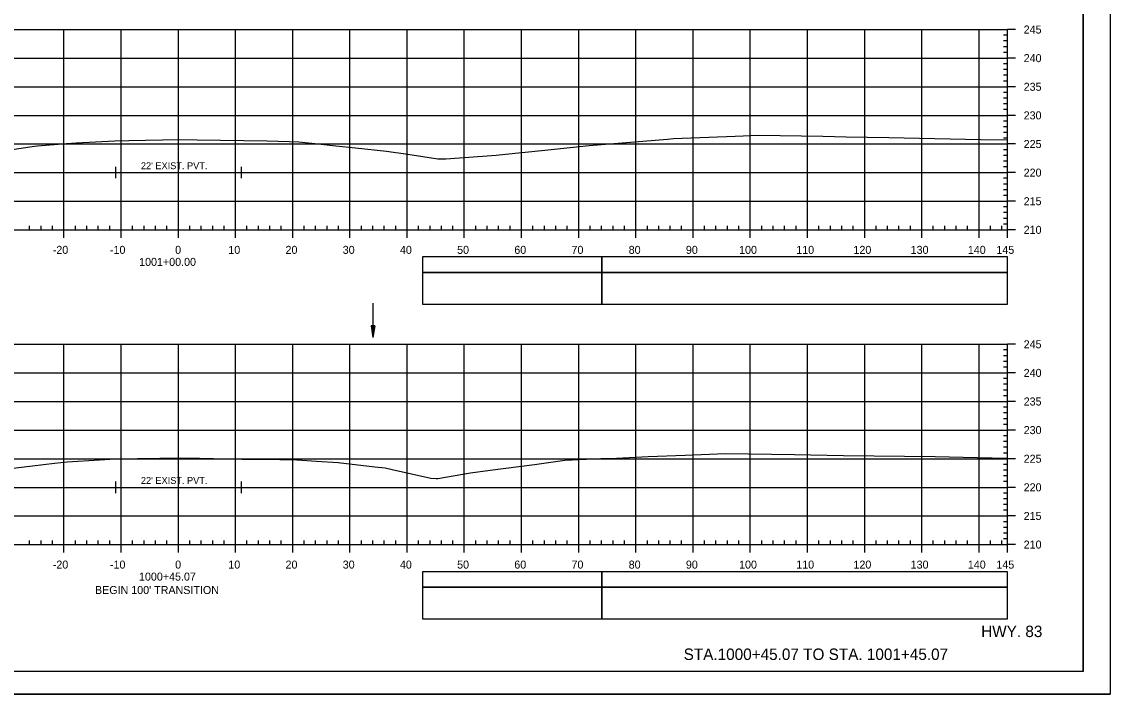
# Model space of a CAD drawing. Extents: x 1386544 to 1388153, y 379785 to 390999.
# Drawn here: x 1387350.6 to 1387540.9, y 379784.8 to 379902.3 of the extents above; entities that cross this region are included whole.
import ezdxf

# ---------------------------------------------------------------- set-up
doc = ezdxf.new("R2010")
doc.units = 0
for name, color, linetype in [('R_Alt Surface', 7, 'Continuous'), ('R_Axis', 7, 'Continuous'), ('R_Axis Annot', 7, 'Continuous'), ('R_Border', 7, 'Continuous'), ('R_Draft', 7, 'Continuous'), ('R_Exist Surface', 7, 'Continuous'), ('R_Grid', 7, 'Continuous'), ('R_No Plot', 7, 'Continuous'), ('R_Striping', 7, 'Continuous'), ('R_Water', 7, 'Continuous')]:
    doc.layers.add(name, color=color, linetype=linetype)

msp = doc.modelspace()

# ---------------------------------------------------------------- linework, layer by layer
at = {"layer": 'R_Alt Surface'}
for points in [[(1387366.95, 379876.95), (1387366.95, 379874.95)], [(1387388.95, 379876.95), (1387388.95, 379874.95)], [(1387366.95, 379875.95), (1387388.95, 379875.95)], [(1387366.95, 379821.95), (1387366.95, 379819.95)], [(1387388.95, 379821.95), (1387388.95, 379819.95)], [(1387366.95, 379820.95), (1387388.95, 379820.95)]]:
    msp.add_lwpolyline(points, dxfattribs=at)
at = {"layer": 'R_Axis'}
for p, q in [((1387522.95, 379899.95), (1387522.25, 379899.95)), ((1387522.95, 379865.95), (1387522.95, 379900.95)), ((1387524.35, 379900.95), (1387522.95, 379900.95)), ((1387522.95, 379898.95), (1387522.25, 379898.95)), ((1387522.95, 379897.95), (1387522.25, 379897.95)), ((1387522.95, 379896.95), (1387522.25, 379896.95)), ((1387522.95, 379894.95), (1387522.25, 379894.95)), ((1387524.35, 379895.95), (1387522.95, 379895.95)), ((1387522.95, 379893.95), (1387522.25, 379893.95)), ((1387522.95, 379892.95), (1387522.25, 379892.95)), ((1387522.95, 379891.95), (1387522.25, 379891.95)), ((1387524.35, 379890.95), (1387522.95, 379890.95)), ((1387522.95, 379889.95), (1387522.25, 379889.95)), ((1387522.95, 379888.95), (1387522.25, 379888.95)), ((1387522.95, 379887.95), (1387522.25, 379887.95)), ((1387522.95, 379886.95), (1387522.25, 379886.95)), ((1387522.95, 379884.95), (1387522.25, 379884.95)), ((1387524.35, 379885.95), (1387522.95, 379885.95)), ((1387522.95, 379883.95), (1387522.25, 379883.95)), ((1387522.95, 379882.95), (1387522.25, 379882.95)), ((1387522.95, 379881.95), (1387522.25, 379881.95)), ((1387524.35, 379880.95), (1387522.95, 379880.95)), ((1387522.95, 379879.95), (1387522.25, 379879.95)), ((1387522.95, 379878.95), (1387522.25, 379878.95)), ((1387522.95, 379877.95), (1387522.25, 379877.95)), ((1387522.95, 379876.95), (1387522.25, 379876.95)), ((1387524.35, 379875.95), (1387522.95, 379875.95)), ((1387522.95, 379874.95), (1387522.25, 379874.95)), ((1387522.95, 379873.95), (1387522.25, 379873.95)), ((1387522.95, 379872.95), (1387522.25, 379872.95)), ((1387522.95, 379871.95), (1387522.25, 379871.95)), ((1387522.95, 379869.95), (1387522.25, 379869.95)), ((1387524.35, 379870.95), (1387522.95, 379870.95)), ((1387522.95, 379868.95), (1387522.25, 379868.95)), ((1387522.95, 379867.95), (1387522.25, 379867.95)), ((1387232.95, 379865.95), (1387522.95, 379865.95)), ((1387351.95, 379865.95), (1387351.95, 379866.65)), ((1387353.95, 379865.95), (1387353.95, 379866.65)), ((1387355.95, 379865.95), (1387355.95, 379866.65)), ((1387357.95, 379864.55), (1387357.95, 379865.95)), ((1387359.95, 379865.95), (1387359.95, 379866.65)), ((1387361.95, 379865.95), (1387361.95, 379866.65)), ((1387363.95, 379865.95), (1387363.95, 379866.65)), ((1387365.95, 379865.95), (1387365.95, 379866.65)), ((1387367.95, 379864.55), (1387367.95, 379865.95)), ((1387369.95, 379865.95), (1387369.95, 379866.65)), ((1387371.95, 379865.95), (1387371.95, 379866.65)), ((1387373.95, 379865.95), (1387373.95, 379866.65)), ((1387375.95, 379865.95), (1387375.95, 379866.65)), ((1387377.95, 379864.55), (1387377.95, 379865.95)), ((1387379.95, 379865.95), (1387379.95, 379866.65)), ((1387381.95, 379865.95), (1387381.95, 379866.65)), ((1387383.95, 379865.95), (1387383.95, 379866.65)), ((1387385.95, 379865.95), (1387385.95, 379866.65)), ((1387387.95, 379864.55), (1387387.95, 379865.95)), ((1387389.95, 379865.95), (1387389.95, 379866.65)), ((1387391.95, 379865.95), (1387391.95, 379866.65)), ((1387393.95, 379865.95), (1387393.95, 379866.65)), ((1387395.95, 379865.95), (1387395.95, 379866.65)), ((1387397.95, 379864.55), (1387397.95, 379865.95)), ((1387399.95, 379865.95), (1387399.95, 379866.65)), ((1387401.95, 379865.95), (1387401.95, 379866.65)), ((1387403.95, 379865.95), (1387403.95, 379866.65)), ((1387405.95, 379865.95), (1387405.95, 379866.65)), ((1387407.95, 379864.55), (1387407.95, 379865.95)), ((1387409.95, 379865.95), (1387409.95, 379866.65)), ((1387411.95, 379865.95), (1387411.95, 379866.65)), ((1387413.95, 379865.95), (1387413.95, 379866.65)), ((1387415.95, 379865.95), (1387415.95, 379866.65)), ((1387417.95, 379864.55), (1387417.95, 379865.95)), ((1387419.95, 379865.95), (1387419.95, 379866.65)), ((1387421.95, 379865.95), (1387421.95, 379866.65)), ((1387423.95, 379865.95), (1387423.95, 379866.65)), ((1387425.95, 379865.95), (1387425.95, 379866.65)), ((1387427.95, 379864.55), (1387427.95, 379865.95)), ((1387429.95, 379865.95), (1387429.95, 379866.65)), ((1387431.95, 379865.95), (1387431.95, 379866.65)), ((1387433.95, 379865.95), (1387433.95, 379866.65)), ((1387435.95, 379865.95), (1387435.95, 379866.65)), ((1387437.95, 379864.55), (1387437.95, 379865.95)), ((1387439.95, 379865.95), (1387439.95, 379866.65)), ((1387441.95, 379865.95), (1387441.95, 379866.65)), ((1387443.95, 379865.95), (1387443.95, 379866.65)), ((1387445.95, 379865.95), (1387445.95, 379866.65)), ((1387447.95, 379864.55), (1387447.95, 379865.95)), ((1387449.95, 379865.95), (1387449.95, 379866.65)), ((1387451.95, 379865.95), (1387451.95, 379866.65)), ((1387453.95, 379865.95), (1387453.95, 379866.65)), ((1387455.95, 379865.95), (1387455.95, 379866.65)), ((1387457.95, 379864.55), (1387457.95, 379865.95)), ((1387459.95, 379865.95), (1387459.95, 379866.65)), ((1387461.95, 379865.95), (1387461.95, 379866.65)), ((1387463.95, 379865.95), (1387463.95, 379866.65)), ((1387465.95, 379865.95), (1387465.95, 379866.65)), ((1387467.95, 379864.55), (1387467.95, 379865.95)), ((1387469.95, 379865.95), (1387469.95, 379866.65)), ((1387471.95, 379865.95), (1387471.95, 379866.65)), ((1387473.95, 379865.95), (1387473.95, 379866.65)), ((1387475.95, 379865.95), (1387475.95, 379866.65)), ((1387477.95, 379864.55), (1387477.95, 379865.95)), ((1387479.95, 379865.95), (1387479.95, 379866.65)), ((1387481.95, 379865.95), (1387481.95, 379866.65)), ((1387483.95, 379865.95), (1387483.95, 379866.65)), ((1387485.95, 379865.95), (1387485.95, 379866.65)), ((1387487.95, 379864.55), (1387487.95, 379865.95)), ((1387489.95, 379865.95), (1387489.95, 379866.65)), ((1387491.95, 379865.95), (1387491.95, 379866.65)), ((1387493.95, 379865.95), (1387493.95, 379866.65)), ((1387495.95, 379865.95), (1387495.95, 379866.65)), ((1387497.95, 379864.55), (1387497.95, 379865.95)), ((1387499.95, 379865.95), (1387499.95, 379866.65)), ((1387501.95, 379865.95), (1387501.95, 379866.65)), ((1387503.95, 379865.95), (1387503.95, 379866.65)), ((1387505.95, 379865.95), (1387505.95, 379866.65)), ((1387507.95, 379864.55), (1387507.95, 379865.95)), ((1387509.95, 379865.95), (1387509.95, 379866.65)), ((1387511.95, 379865.95), (1387511.95, 379866.65)), ((1387513.95, 379865.95), (1387513.95, 379866.65)), ((1387515.95, 379865.95), (1387515.95, 379866.65)), ((1387517.95, 379864.55), (1387517.95, 379865.95)), ((1387519.95, 379865.95), (1387519.95, 379866.65)), ((1387521.95, 379865.95), (1387521.95, 379866.65)), ((1387522.95, 379866.95), (1387522.25, 379866.95)), ((1387522.95, 379864.55), (1387522.95, 379865.95)), ((1387524.35, 379865.95), (1387522.95, 379865.95)), ((1387522.95, 379844.95), (1387522.25, 379844.95)), ((1387522.95, 379810.95), (1387522.95, 379845.95)), ((1387524.35, 379845.95), (1387522.95, 379845.95)), ((1387522.95, 379843.95), (1387522.25, 379843.95)), ((1387522.95, 379842.95), (1387522.25, 379842.95)), ((1387522.95, 379841.95), (1387522.25, 379841.95)), ((1387524.35, 379840.95), (1387522.95, 379840.95)), ((1387522.95, 379839.95), (1387522.25, 379839.95)), ((1387522.95, 379838.95), (1387522.25, 379838.95)), ((1387522.95, 379837.95), (1387522.25, 379837.95)), ((1387522.95, 379836.95), (1387522.25, 379836.95)), ((1387524.35, 379835.95), (1387522.95, 379835.95)), ((1387522.95, 379834.95), (1387522.25, 379834.95)), ((1387522.95, 379833.95), (1387522.25, 379833.95)), ((1387522.95, 379832.95), (1387522.25, 379832.95)), ((1387522.95, 379831.95), (1387522.25, 379831.95)), ((1387522.95, 379829.95), (1387522.25, 379829.95)), ((1387524.35, 379830.95), (1387522.95, 379830.95)), ((1387522.95, 379828.95), (1387522.25, 379828.95)), ((1387522.95, 379827.95), (1387522.25, 379827.95)), ((1387522.95, 379826.95), (1387522.25, 379826.95)), ((1387524.35, 379825.95), (1387522.95, 379825.95)), ((1387522.95, 379824.95), (1387522.25, 379824.95)), ((1387522.95, 379823.95), (1387522.25, 379823.95)), ((1387522.95, 379822.95), (1387522.25, 379822.95)), ((1387522.95, 379821.95), (1387522.25, 379821.95)), ((1387522.95, 379819.95), (1387522.25, 379819.95)), ((1387524.35, 379820.95), (1387522.95, 379820.95)), ((1387522.95, 379818.95), (1387522.25, 379818.95)), ((1387522.95, 379817.95), (1387522.25, 379817.95)), ((1387522.95, 379816.95), (1387522.25, 379816.95)), ((1387522.95, 379814.95), (1387522.25, 379814.95)), ((1387524.35, 379815.95), (1387522.95, 379815.95)), ((1387522.95, 379813.95), (1387522.25, 379813.95)), ((1387522.95, 379812.95), (1387522.25, 379812.95)), ((1387232.95, 379810.95), (1387522.95, 379810.95)), ((1387351.95, 379810.95), (1387351.95, 379811.65)), ((1387353.95, 379810.95), (1387353.95, 379811.65)), ((1387355.95, 379810.95), (1387355.95, 379811.65)), ((1387357.95, 379809.55), (1387357.95, 379810.95)), ((1387359.95, 379810.95), (1387359.95, 379811.65)), ((1387361.95, 379810.95), (1387361.95, 379811.65)), ((1387363.95, 379810.95), (1387363.95, 379811.65)), ((1387365.95, 379810.95), (1387365.95, 379811.65)), ((1387367.95, 379809.55), (1387367.95, 379810.95)), ((1387369.95, 379810.95), (1387369.95, 379811.65)), ((1387371.95, 379810.95), (1387371.95, 379811.65)), ((1387373.95, 379810.95), (1387373.95, 379811.65)), ((1387375.95, 379810.95), (1387375.95, 379811.65)), ((1387377.95, 379809.55), (1387377.95, 379810.95)), ((1387379.95, 379810.95), (1387379.95, 379811.65)), ((1387381.95, 379810.95), (1387381.95, 379811.65)), ((1387383.95, 379810.95), (1387383.95, 379811.65)), ((1387385.95, 379810.95), (1387385.95, 379811.65)), ((1387387.95, 379809.55), (1387387.95, 379810.95)), ((1387389.95, 379810.95), (1387389.95, 379811.65)), ((1387391.95, 379810.95), (1387391.95, 379811.65)), ((1387393.95, 379810.95), (1387393.95, 379811.65)), ((1387395.95, 379810.95), (1387395.95, 379811.65)), ((1387397.95, 379809.55), (1387397.95, 379810.95)), ((1387399.95, 379810.95), (1387399.95, 379811.65)), ((1387401.95, 379810.95), (1387401.95, 379811.65)), ((1387403.95, 379810.95), (1387403.95, 379811.65)), ((1387405.95, 379810.95), (1387405.95, 379811.65)), ((1387407.95, 379809.55), (1387407.95, 379810.95)), ((1387409.95, 379810.95), (1387409.95, 379811.65)), ((1387411.95, 379810.95), (1387411.95, 379811.65)), ((1387413.95, 379810.95), (1387413.95, 379811.65)), ((1387415.95, 379810.95), (1387415.95, 379811.65)), ((1387417.95, 379809.55), (1387417.95, 379810.95)), ((1387419.95, 379810.95), (1387419.95, 379811.65)), ((1387421.95, 379810.95), (1387421.95, 379811.65)), ((1387423.95, 379810.95), (1387423.95, 379811.65)), ((1387425.95, 379810.95), (1387425.95, 379811.65)), ((1387427.95, 379809.55), (1387427.95, 379810.95)), ((1387429.95, 379810.95), (1387429.95, 379811.65)), ((1387431.95, 379810.95), (1387431.95, 379811.65)), ((1387433.95, 379810.95), (1387433.95, 379811.65)), ((1387435.95, 379810.95), (1387435.95, 379811.65)), ((1387437.95, 379809.55), (1387437.95, 379810.95)), ((1387439.95, 379810.95), (1387439.95, 379811.65)), ((1387441.95, 379810.95), (1387441.95, 379811.65)), ((1387443.95, 379810.95), (1387443.95, 379811.65)), ((1387445.95, 379810.95), (1387445.95, 379811.65)), ((1387447.95, 379809.55), (1387447.95, 379810.95)), ((1387449.95, 379810.95), (1387449.95, 379811.65)), ((1387451.95, 379810.95), (1387451.95, 379811.65)), ((1387453.95, 379810.95), (1387453.95, 379811.65)), ((1387455.95, 379810.95), (1387455.95, 379811.65)), ((1387457.95, 379809.55), (1387457.95, 379810.95)), ((1387459.95, 379810.95), (1387459.95, 379811.65)), ((1387461.95, 379810.95), (1387461.95, 379811.65)), ((1387463.95, 379810.95), (1387463.95, 379811.65)), ((1387465.95, 379810.95), (1387465.95, 379811.65)), ((1387467.95, 379809.55), (1387467.95, 379810.95)), ((1387469.95, 379810.95), (1387469.95, 379811.65)), ((1387471.95, 379810.95), (1387471.95, 379811.65)), ((1387473.95, 379810.95), (1387473.95, 379811.65)), ((1387475.95, 379810.95), (1387475.95, 379811.65)), ((1387477.95, 379809.55), (1387477.95, 379810.95)), ((1387479.95, 379810.95), (1387479.95, 379811.65)), ((1387481.95, 379810.95), (1387481.95, 379811.65)), ((1387483.95, 379810.95), (1387483.95, 379811.65)), ((1387485.95, 379810.95), (1387485.95, 379811.65)), ((1387487.95, 379809.55), (1387487.95, 379810.95)), ((1387489.95, 379810.95), (1387489.95, 379811.65)), ((1387491.95, 379810.95), (1387491.95, 379811.65)), ((1387493.95, 379810.95), (1387493.95, 379811.65)), ((1387495.95, 379810.95), (1387495.95, 379811.65)), ((1387497.95, 379809.55), (1387497.95, 379810.95)), ((1387499.95, 379810.95), (1387499.95, 379811.65)), ((1387501.95, 379810.95), (1387501.95, 379811.65)), ((1387503.95, 379810.95), (1387503.95, 379811.65)), ((1387505.95, 379810.95), (1387505.95, 379811.65)), ((1387507.95, 379809.55), (1387507.95, 379810.95)), ((1387509.95, 379810.95), (1387509.95, 379811.65)), ((1387511.95, 379810.95), (1387511.95, 379811.65)), ((1387513.95, 379810.95), (1387513.95, 379811.65)), ((1387515.95, 379810.95), (1387515.95, 379811.65)), ((1387517.95, 379809.55), (1387517.95, 379810.95)), ((1387519.95, 379810.95), (1387519.95, 379811.65)), ((1387521.95, 379810.95), (1387521.95, 379811.65)), ((1387522.95, 379811.95), (1387522.25, 379811.95)), ((1387522.95, 379809.55), (1387522.95, 379810.95)), ((1387524.35, 379810.95), (1387522.95, 379810.95))]:
    msp.add_line(p, q, dxfattribs=at)
at = {"layer": 'R_Axis Annot'}
for points in [[(1387451.97, 379858.5), (1387522.95, 379858.5), (1387522.95, 379861.21), (1387451.97, 379861.21)], [(1387451.97, 379852.98), (1387522.95, 379852.98), (1387522.95, 379858.5), (1387451.97, 379858.5)], [(1387451.97, 379803.5), (1387522.95, 379803.5), (1387522.95, 379806.21), (1387451.97, 379806.21)], [(1387451.97, 379797.98), (1387522.95, 379797.98), (1387522.95, 379803.5), (1387451.97, 379803.5)]]:
    msp.add_lwpolyline(points, close=True, dxfattribs=at)
at = {"layer": 'R_Border'}
for q in [(1387536.13, 379994.24), (1387219.95, 379788.78)]:
    msp.add_line((1387536.13, 379788.78), q, dxfattribs=at)
at = {"layer": 'R_Exist Surface'}
for points in [[(1387337.3, 379878.22), (1387351.98, 379880.44), (1387352.77, 379880.56), (1387353.33, 379880.61), (1387358.41, 379881.06), (1387360.08, 379881.16), (1387366.83, 379881.51), (1387369.28, 379881.55), (1387378.08, 379881.71), (1387381.21, 379881.67), (1387393.48, 379881.49), (1387397.31, 379881.4), (1387399.01, 379881.35), (1387402.42, 379880.97), (1387405.46, 379880.64), (1387408.92, 379880.28), (1387414.33, 379879.71), (1387418.08, 379879.15), (1387423.33, 379878.38), (1387424.19, 379878.38), (1387424.73, 379878.38), (1387433.51, 379879), (1387435.12, 379879.15), (1387441.47, 379879.8), (1387449.76, 379880.66), (1387463.5, 379881.79), (1387464.54, 379881.89), (1387475.28, 379882.33), (1387479.47, 379882.52), (1387490.66, 379882.3), (1387494.74, 379882.21), (1387502.18, 379882.06), (1387518.27, 379881.74), (1387522.95, 379881.68)], [(1387338.29, 379822.99), (1387352.44, 379824.68), (1387356.28, 379825.16), (1387358.49, 379825.42), (1387364.18, 379825.76), (1387366.91, 379825.94), (1387374.69, 379826.07), (1387378.24, 379826.12), (1387381.63, 379826.05), (1387389.07, 379825.89), (1387395.72, 379825.81), (1387398.65, 379825.76), (1387402.09, 379825.5), (1387405.92, 379825.27), (1387412.31, 379824.52), (1387414.08, 379824.33), (1387415.32, 379824.07), (1387422.09, 379822.54), (1387423.02, 379822.48), (1387423.33, 379822.47), (1387429.04, 379823.46), (1387432.44, 379823.93), (1387440.24, 379824.95), (1387445.52, 379825.72), (1387451.79, 379825.99), (1387454.53, 379826.07), (1387460.09, 379826.33), (1387466.59, 379826.6), (1387473.62, 379826.88), (1387485.7, 379826.7), (1387494.26, 379826.53), (1387510.28, 379826.31), (1387517.6, 379826.17), (1387522.95, 379826.05)]]:
    msp.add_lwpolyline(points, dxfattribs=at)
at = {"layer": 'R_Grid'}
for p, q in [((1387232.95, 379900.95), (1387522.95, 379900.95)), ((1387357.95, 379865.95), (1387357.95, 379900.95)), ((1387367.95, 379865.95), (1387367.95, 379900.95)), ((1387377.95, 379865.95), (1387377.95, 379900.95)), ((1387387.95, 379865.95), (1387387.95, 379900.95)), ((1387397.95, 379865.95), (1387397.95, 379900.95)), ((1387407.95, 379865.95), (1387407.95, 379900.95)), ((1387417.95, 379865.95), (1387417.95, 379900.95)), ((1387427.95, 379865.95), (1387427.95, 379900.95)), ((1387437.95, 379865.95), (1387437.95, 379900.95)), ((1387447.95, 379865.95), (1387447.95, 379900.95)), ((1387457.95, 379865.95), (1387457.95, 379900.95)), ((1387467.95, 379865.95), (1387467.95, 379900.95)), ((1387477.95, 379865.95), (1387477.95, 379900.95)), ((1387487.95, 379865.95), (1387487.95, 379900.95)), ((1387497.95, 379865.95), (1387497.95, 379900.95)), ((1387507.95, 379865.95), (1387507.95, 379900.95)), ((1387517.95, 379865.95), (1387517.95, 379900.95)), ((1387522.95, 379865.95), (1387522.95, 379900.95)), ((1387232.95, 379895.95), (1387522.95, 379895.95)), ((1387232.95, 379890.95), (1387522.95, 379890.95)), ((1387232.95, 379885.95), (1387522.95, 379885.95)), ((1387232.95, 379880.95), (1387522.95, 379880.95)), ((1387232.95, 379875.95), (1387522.95, 379875.95)), ((1387232.95, 379870.95), (1387522.95, 379870.95)), ((1387232.95, 379865.95), (1387522.95, 379865.95)), ((1387232.95, 379845.95), (1387522.95, 379845.95)), ((1387357.95, 379810.95), (1387357.95, 379845.95)), ((1387367.95, 379810.95), (1387367.95, 379845.95)), ((1387377.95, 379810.95), (1387377.95, 379845.95)), ((1387387.95, 379810.95), (1387387.95, 379845.95)), ((1387397.95, 379810.95), (1387397.95, 379845.95)), ((1387407.95, 379810.95), (1387407.95, 379845.95)), ((1387417.95, 379810.95), (1387417.95, 379845.95)), ((1387427.95, 379810.95), (1387427.95, 379845.95)), ((1387437.95, 379810.95), (1387437.95, 379845.95)), ((1387447.95, 379810.95), (1387447.95, 379845.95)), ((1387457.95, 379810.95), (1387457.95, 379845.95)), ((1387467.95, 379810.95), (1387467.95, 379845.95)), ((1387477.95, 379810.95), (1387477.95, 379845.95)), ((1387487.95, 379810.95), (1387487.95, 379845.95)), ((1387497.95, 379810.95), (1387497.95, 379845.95)), ((1387507.95, 379810.95), (1387507.95, 379845.95)), ((1387517.95, 379810.95), (1387517.95, 379845.95)), ((1387522.95, 379810.95), (1387522.95, 379845.95)), ((1387232.95, 379840.95), (1387522.95, 379840.95)), ((1387232.95, 379835.95), (1387522.95, 379835.95)), ((1387232.95, 379830.95), (1387522.95, 379830.95)), ((1387232.95, 379825.95), (1387522.95, 379825.95)), ((1387232.95, 379820.95), (1387522.95, 379820.95)), ((1387232.95, 379815.95), (1387522.95, 379815.95)), ((1387232.95, 379810.95), (1387522.95, 379810.95))]:
    msp.add_line(p, q, dxfattribs=at)
at = {"layer": 'R_No Plot'}
msp.add_line((1387207.55, 379784.8), (1387540.89, 379784.8), dxfattribs=at)
for points in [[(1387207.55, 379998.13), (1387540.89, 379998.13), (1387540.89, 379784.8), (1387207.55, 379784.8)], [(1387453.87, 379994.24), (1387473.49, 379994.24), (1387473.49, 379984.36), (1387489.6, 379984.36), (1387512.8, 379984.36), (1387512.8, 379960.03), (1387536.13, 379960.03), (1387536.13, 379788.78), (1387219.95, 379788.78), (1387219.95, 379994.24)]]:
    msp.add_lwpolyline(points, close=True, dxfattribs=at)
at = {"layer": 'R_Striping'}
for points in [[(1387420.63, 379858.51), (1387451.97, 379858.51), (1387451.97, 379861.21), (1387420.63, 379861.21)], [(1387420.63, 379852.98), (1387451.97, 379852.98), (1387451.97, 379858.51), (1387420.63, 379858.51)], [(1387420.63, 379803.51), (1387451.97, 379803.51), (1387451.97, 379806.21), (1387420.63, 379806.21)], [(1387420.63, 379797.98), (1387451.97, 379797.98), (1387451.97, 379803.51), (1387420.63, 379803.51)]]:
    msp.add_lwpolyline(points, close=True, dxfattribs=at)
at = {"layer": 'R_Water'}
for p, q in [((1387411.98, 379853.16), (1387411.98, 379847.16)), ((1387411.68, 379849.16), (1387411.98, 379847.16)), ((1387412.28, 379849.16), (1387411.68, 379849.16)), ((1387411.68, 379849.16), (1387411.98, 379847.16)), ((1387412.28, 379849.16), (1387411.68, 379849.16)), ((1387411.73, 379849.16), (1387411.98, 379847.49)), ((1387411.73, 379849.16), (1387411.98, 379847.49)), ((1387411.78, 379849.16), (1387411.98, 379847.84)), ((1387411.78, 379849.16), (1387411.98, 379847.84)), ((1387411.83, 379849.16), (1387411.98, 379848.17)), ((1387411.83, 379849.16), (1387411.98, 379848.17)), ((1387411.89, 379849.16), (1387411.98, 379848.51)), ((1387411.89, 379849.16), (1387411.98, 379848.51)), ((1387411.94, 379849.16), (1387411.98, 379848.84)), ((1387411.94, 379849.16), (1387411.98, 379848.84)), ((1387412.28, 379849.16), (1387411.98, 379847.16)), ((1387412.08, 379849.16), (1387411.98, 379848.51)), ((1387412.18, 379849.16), (1387411.98, 379847.84)), ((1387412.23, 379849.16), (1387411.98, 379847.49)), ((1387412.13, 379849.16), (1387411.98, 379848.17)), ((1387412.03, 379849.16), (1387411.98, 379848.84)), ((1387412.28, 379849.16), (1387411.98, 379847.16)), ((1387412.08, 379849.16), (1387411.98, 379848.51)), ((1387412.18, 379849.16), (1387411.98, 379847.84)), ((1387412.23, 379849.16), (1387411.98, 379847.49)), ((1387412.13, 379849.16), (1387411.98, 379848.17)), ((1387412.03, 379849.16), (1387411.98, 379848.84))]:
    msp.add_line(p, q, dxfattribs=at)

# ---------------------------------------------------------------- texts
at = {"layer": 'R_Axis Annot'}
for s, p in [('245', (1387525.75, 379900.25)), ('240', (1387525.75, 379895.25)), ('235', (1387525.75, 379890.25)), ('230', (1387525.75, 379885.25)), ('225', (1387525.75, 379880.25)), ('220', (1387525.75, 379875.25)), ('215', (1387525.75, 379870.25)), ('210', (1387525.75, 379865.25)), ('-20', (1387355.99, 379861.75)), ('-10', (1387365.99, 379861.75)), ('0', (1387377.39, 379861.75)), ('10', (1387386.69, 379861.75)), ('20', (1387396.69, 379861.75)), ('30', (1387406.69, 379861.75)), ('40', (1387416.69, 379861.75)), ('50', (1387426.69, 379861.75)), ('60', (1387436.69, 379861.75)), ('70', (1387446.69, 379861.75)), ('80', (1387456.69, 379861.75)), ('90', (1387466.69, 379861.75)), ('100', (1387475.99, 379861.75)), ('110', (1387485.99, 379861.75)), ('120', (1387495.99, 379861.75)), ('130', (1387505.99, 379861.75)), ('140', (1387515.99, 379861.75)), ('145', (1387520.98, 379861.75)), ('1001+00.00', (1387371.09, 379859.65)), ('245', (1387525.75, 379845.25)), ('240', (1387525.75, 379840.25)), ('235', (1387525.75, 379835.25)), ('230', (1387525.75, 379830.25)), ('225', (1387525.75, 379825.25)), ('220', (1387525.75, 379820.25)), ('215', (1387525.75, 379815.25)), ('210', (1387525.75, 379810.25)), ('-20', (1387355.99, 379806.75)), ('-10', (1387365.99, 379806.75)), ('0', (1387377.39, 379806.75)), ('10', (1387386.69, 379806.75)), ('20', (1387396.69, 379806.75)), ('30', (1387406.69, 379806.75)), ('40', (1387416.69, 379806.75)), ('50', (1387426.69, 379806.75)), ('60', (1387436.69, 379806.75)), ('70', (1387446.69, 379806.75)), ('80', (1387456.69, 379806.75)), ('90', (1387466.69, 379806.75)), ('100', (1387475.99, 379806.75)), ('110', (1387485.99, 379806.75)), ('120', (1387495.99, 379806.75)), ('130', (1387505.99, 379806.75)), ('140', (1387515.99, 379806.75)), ('145', (1387520.98, 379806.75)), ('1000+45.07', (1387371.07, 379804.65)), ("BEGIN 100' TRANSITION", (1387363.37, 379802.31))]:
    msp.add_text(s, height=1.4, dxfattribs=at).set_placement(p)
at = {"layer": 'R_Draft'}
for s, p in [('HWY. 83', (1387518.32, 379794.78)), ('STA.1000+45.07 TO STA. 1001+45.07', (1387466.3, 379790.78))]:
    msp.add_text(s, height=2, dxfattribs=at).set_placement(p)
at = {"layer": 'R_Water'}
for p in [(1387371.4, 379876.55), (1387371.4, 379821.55)]:
    msp.add_text("22' EXIST. PVT.", height=1.2, dxfattribs=at).set_placement(p)

doc.saveas('drawing.dxf')
